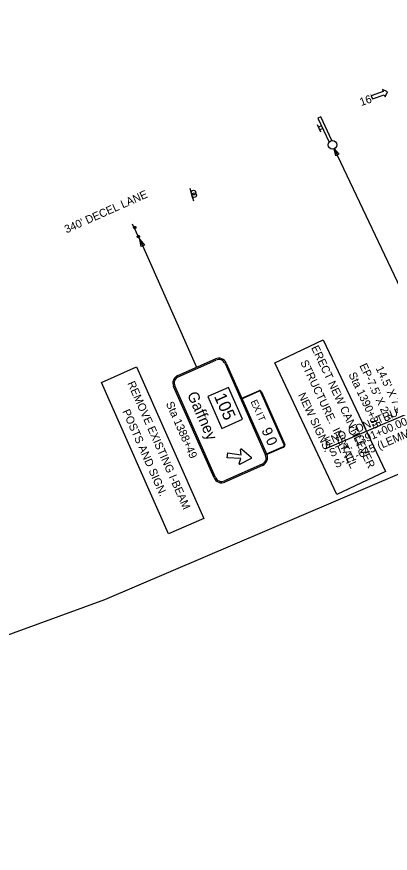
# Model space of a CAD drawing. Extents: x 1786955 to 1788674, y 1181944 to 1183335.
# Drawn here: x 1787825 to 1788151, y 1181944 to 1182676 of the extents above; entities that cross this region are included whole.
import ezdxf

# ---------------------------------------------------------------- set-up
doc = ezdxf.new("R2010")
doc.units = 0
for name, color, linetype in [('RD_PD_Final_LnLine', 7, 'Continuous'), ('RD_PD_Final_TX', 7, 'Continuous'), ('RD_SHT_ShtClip', 7, 'Continuous'), ('SN_P_Signs', 7, 'Continuous')]:
    doc.layers.add(name, color=color, linetype=linetype)

# ---------------------------------------------------------------- blocks, each defined once
blk = doc.blocks.new('SARRW2')
at = {"layer": 'RD_PD_Final_LnLine'}
blk.add_lwpolyline([(-12, 1.2), (-12, -1.2), (-2.83, -1.2), (-2.83, -2.83), (0, 0), (-2.83, 2.83), (-2.83, 1.2)], close=True, dxfattribs=at)

msp = doc.modelspace()

# ---------------------------------------------------------------- linework, layer by layer
at = {"layer": 'RD_PD_Final_TX'}
msp.add_line((1788216.18, 1182349.73), (1788094.11, 1182297.56), dxfattribs=at)
at = {"layer": 'RD_SHT_ShtClip'}
msp.add_lwpolyline([(1788602.87, 1182624.64), (1788373.62, 1183042.27), (1788169.17, 1183137.08), (1788110.36, 1183228.48), (1786954.94, 1182732.25), (1787147.48, 1182122.09), (1787221.15, 1182060.45), (1787293.74, 1181944.03), (1787901.65, 1182166), (1788673.56, 1182495.86)], close=True, dxfattribs=at)
at = {"layer": 'SN_P_Signs'}
for p, q in [((1788090.71, 1182575.03), (1788087.74, 1182581.32)), ((1788091.17, 1182580.53), (1788088.65, 1182579.34)), ((1788092.31, 1182578.11), (1788089.81, 1182576.92)), ((1788102.41, 1182560.53), (1788173.24, 1182410.52)), ((1787976.19, 1182525.96), (1787978.5, 1182517.27)), ((1787976.62, 1182523.58), (1787979.29, 1182514.99)), ((1787932.49, 1182481.06), (1787926.06, 1182494.4)), ((1787927.22, 1182492.29), (1787928.63, 1182490.88)), ((1787927.22, 1182490.88), (1787928.63, 1182492.29)), ((1787930.41, 1182484.27), (1787931.82, 1182482.86)), ((1787930.41, 1182482.86), (1787931.82, 1182484.27)), ((1787932.49, 1182481.06), (1787981.96, 1182369.34)), ((1788050.31, 1182373.26), (1788092.64, 1182393.24)), ((1788092.64, 1182393.24), (1788147.06, 1182277.99)), ((1788104.73, 1182258.01), (1788050.31, 1182373.26)), ((1787898.83, 1182356.05), (1787929.57, 1182369.66)), ((1787929.57, 1182369.66), (1787988.28, 1182237.06)), ((1787957.54, 1182223.45), (1787898.83, 1182356.05)), ((1788009.82, 1182351.65), (1787991.81, 1182343.67)), ((1788022.16, 1182323.78), (1788009.82, 1182351.65)), ((1787991.81, 1182343.67), (1788004.15, 1182315.8)), ((1788004.15, 1182315.8), (1788022.16, 1182323.78)), ((1788147.06, 1182277.99), (1788104.73, 1182258.01)), ((1787988.28, 1182237.06), (1787957.54, 1182223.45))]:
    msp.add_line(p, q, dxfattribs=at)
for points in [[(1788100.37, 1182567.57), (1788090.5, 1182588.49), (1788087.97, 1182587.29), (1788097.93, 1182566.21)], [(1787927.93, 1182490.58), (1787927.76, 1182490.6), (1787927.6, 1182490.64), (1787927.45, 1182490.71), (1787927.31, 1182490.8), (1787927.18, 1182490.91), (1787927.08, 1182491.05), (1787927.01, 1182491.19), (1787926.95, 1182491.35), (1787926.93, 1182491.52), (1787926.93, 1182491.68), (1787926.96, 1182491.85), (1787927.02, 1182492.01), (1787927.1, 1182492.15), (1787927.21, 1182492.28), (1787927.33, 1182492.39), (1787927.48, 1182492.48), (1787927.63, 1182492.54), (1787927.79, 1182492.58), (1787927.93, 1182492.58)], [(1787927.93, 1182492.58), (1787928.09, 1182492.57), (1787928.25, 1182492.53), (1787928.41, 1182492.46), (1787928.55, 1182492.37), (1787928.67, 1182492.26), (1787928.77, 1182492.12), (1787928.85, 1182491.98), (1787928.9, 1182491.82), (1787928.92, 1182491.65), (1787928.92, 1182491.48), (1787928.89, 1182491.32), (1787928.83, 1182491.16), (1787928.75, 1182491.02), (1787928.64, 1182490.89), (1787928.52, 1182490.78), (1787928.38, 1182490.69), (1787928.22, 1182490.63), (1787928.06, 1182490.59), (1787927.93, 1182490.58)], [(1787931.11, 1182482.57), (1787930.95, 1182482.58), (1787930.78, 1182482.62), (1787930.63, 1182482.69), (1787930.49, 1182482.78), (1787930.37, 1182482.89), (1787930.27, 1182483.03), (1787930.19, 1182483.17), (1787930.14, 1182483.33), (1787930.11, 1182483.5), (1787930.12, 1182483.67), (1787930.15, 1182483.83), (1787930.21, 1182483.99), (1787930.29, 1182484.13), (1787930.39, 1182484.26), (1787930.52, 1182484.37), (1787930.66, 1182484.46), (1787930.82, 1182484.52), (1787930.98, 1182484.56), (1787931.11, 1182484.57)], [(1787931.11, 1182484.57), (1787931.28, 1182484.55), (1787931.44, 1182484.51), (1787931.59, 1182484.44), (1787931.73, 1182484.35), (1787931.85, 1182484.24), (1787931.96, 1182484.1), (1787932.03, 1182483.96), (1787932.09, 1182483.8), (1787932.11, 1182483.63), (1787932.11, 1182483.47), (1787932.08, 1182483.3), (1787932.02, 1182483.14), (1787931.94, 1182483), (1787931.83, 1182482.87), (1787931.71, 1182482.76), (1787931.56, 1182482.67), (1787931.41, 1182482.61), (1787931.25, 1182482.57), (1787931.11, 1182482.57)], [(1787965.5, 1182362.05), (1787998.42, 1182376.62)], [(1787965.99, 1182360.95), (1787998.91, 1182375.53)], [(1788006.82, 1182372.47), (1788042.29, 1182292.37)], [(1788007.92, 1182372.96), (1788043.39, 1182292.86)], [(1787997.3, 1182272.45), (1787961.83, 1182352.55)], [(1787998.4, 1182272.94), (1787962.93, 1182353.03)], [(1788036.58, 1182348.24), (1788021.77, 1182341.68), (1788021.52, 1182342.23), (1788036.34, 1182348.79)], [(1788058.57, 1182301.55), (1788038.16, 1182347.63)], [(1788038.71, 1182347.87), (1788059.12, 1182301.79)], [(1788043.14, 1182293.41), (1788057.96, 1182299.96)], [(1788058.2, 1182299.42), (1788043.39, 1182292.86), (1788043.14, 1182293.41)], [(1788008.84, 1182290.13), (1788009.29, 1182294.31), (1788021.02, 1182292.56)], [(1788021.02, 1182292.56), (1788020.45, 1182296.97)], [(1788021.43, 1182297.5), (1788029.73, 1182290.51)], [(1788039.23, 1182284.46), (1788006.32, 1182269.88)], [(1788020.67, 1182289.35), (1788008.84, 1182290.13)], [(1788019.19, 1182285.17), (1788020.67, 1182289.35)], [(1788029.63, 1182289.52), (1788020.03, 1182284.43)], [(1788039.72, 1182283.36), (1788006.8, 1182268.78)]]:
    msp.add_lwpolyline(points, dxfattribs=at)
for points in [[(1788103.64, 1182554.31), (1788102.41, 1182560.53), (1788106.42, 1182555.62)], [(1787933.57, 1182474.81), (1787932.49, 1182481.06), (1787936.39, 1182476.06)]]:
    msp.add_lwpolyline(points, close=True, dxfattribs=at)
for centre, radius in [((1788100.82, 1182563.89), 3.71), ((1787979.31, 1182522.12), 2), ((1787979.89, 1182519.87), 2)]:
    msp.add_circle(centre, radius, dxfattribs=at)
for centre, radius, start, end in [((1788001.34, 1182370.04), 7.2, 23.88386, 113.88386), ((1788001.34, 1182370.04), 6, 23.88386, 113.88386), ((1787968.42, 1182355.46), 7.2, 113.88386, 203.88386), ((1787968.42, 1182355.46), 6, 113.88386, 203.88386), ((1788037.06, 1182347.15), 1.8, 23.88386, 113.88386), ((1788037.06, 1182347.15), 1.2, 23.88386, 113.88386), ((1788057.47, 1182301.06), 1.2, 293.88386, 23.88386), ((1788057.47, 1182301.06), 1.8, 293.88386, 23.88386), ((1788021.05, 1182297.05), 0.6, 49.86456, 187.32996), ((1788036.8, 1182289.94), 6, 293.88386, 23.88386), ((1788036.8, 1182289.94), 7.2, 293.88386, 23.88386), ((1788019.75, 1182284.96), 0.6, 160.43776, 297.90326), ((1788029.35, 1182290.05), 0.6, 297.90326, 49.86456), ((1788003.89, 1182275.37), 7.2, 203.88386, 293.88386), ((1788003.89, 1182275.37), 6, 203.88386, 293.88386)]:
    msp.add_arc(centre, radius, start, end, dxfattribs=at)

# ---------------------------------------------------------------- block references
at = {"layer": 'RD_PD_Final_LnLine', "xscale": 1.1999999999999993, "yscale": 1.2000000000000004, "rotation": 19.447851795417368}
msp.add_blockref('SARRW2', (1788148.82, 1182610.21), dxfattribs=at)

# ---------------------------------------------------------------- texts
at = {"layer": 'RD_PD_Final_TX'}
for s, rotation, p in [("16'", 19.44785, (1788126, 1182597.76)), ("340' DECEL LANE", 23.94846, (1787868.29, 1182486.39)), ('END CONSTRUCTION', 23.13854, (1788095.6, 1182300.27)), ('S-11-645 (LEMMONS LANE)', 23.13854, (1788103.86, 1182280.95)), ('STA. 1391+00.00', 23.13854, (1788099.73, 1182290.61))]:
    msp.add_text(s, height=7, rotation=rotation, dxfattribs=at).set_placement(p)
at = {"layer": 'SN_P_Signs'}
for s, height, rotation, p in [('ERECT NEW CANTILEVER', 6.9998, 295.27612, (1788081.99, 1182386.41)), ('STRUCTURE.  INSTALL', 6.9998, 295.27612, (1788072.51, 1182373.7)), ("EP-7.5' X 2.5'", 7, 295.27612, (1788124.15, 1182370.75)), ('Sta 1390+35', 7, 295.27612, (1788114.64, 1182363.03)), ("14.5' X 7.5'", 7, 295.27612, (1788138.39, 1182368.45)), ('REMOVE EXISTING I-BEAM', 6.9998, 293.88394, (1787921.29, 1182355.34)), ('Gaffney', 9.6, 293.88386, (1787973.48, 1182345.52)), ('105', 10.8, 293.88386, (1787997, 1182343.89)), ('NEW SIGNS.', 7, 295.27612, (1788070.51, 1182345.13)), ('Sta 1388+49', 7, 293.88394, (1787954.98, 1182337.48)), ('E', 6, 293.88386, (1788029.06, 1182339.3)), ('X', 6, 293.88386, (1788031.14, 1182334.59)), ('POSTS AND SIGN.', 6.9998, 293.88394, (1787916.88, 1182330.73)), ('I', 6, 293.88386, (1788033.9, 1182328.36)), ('T', 6, 293.88386, (1788035.11, 1182325.63)), ('9', 9, 293.88386, (1788038.54, 1182314.17)), ('0', 9, 293.88386, (1788042.23, 1182305.84))]:
    msp.add_text(s, height=height, rotation=rotation, dxfattribs=at).set_placement(p)

doc.saveas('drawing.dxf')
